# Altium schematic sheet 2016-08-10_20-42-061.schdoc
size 331 x 134 mm; SheetNumber: 1; SheetTotal: 1
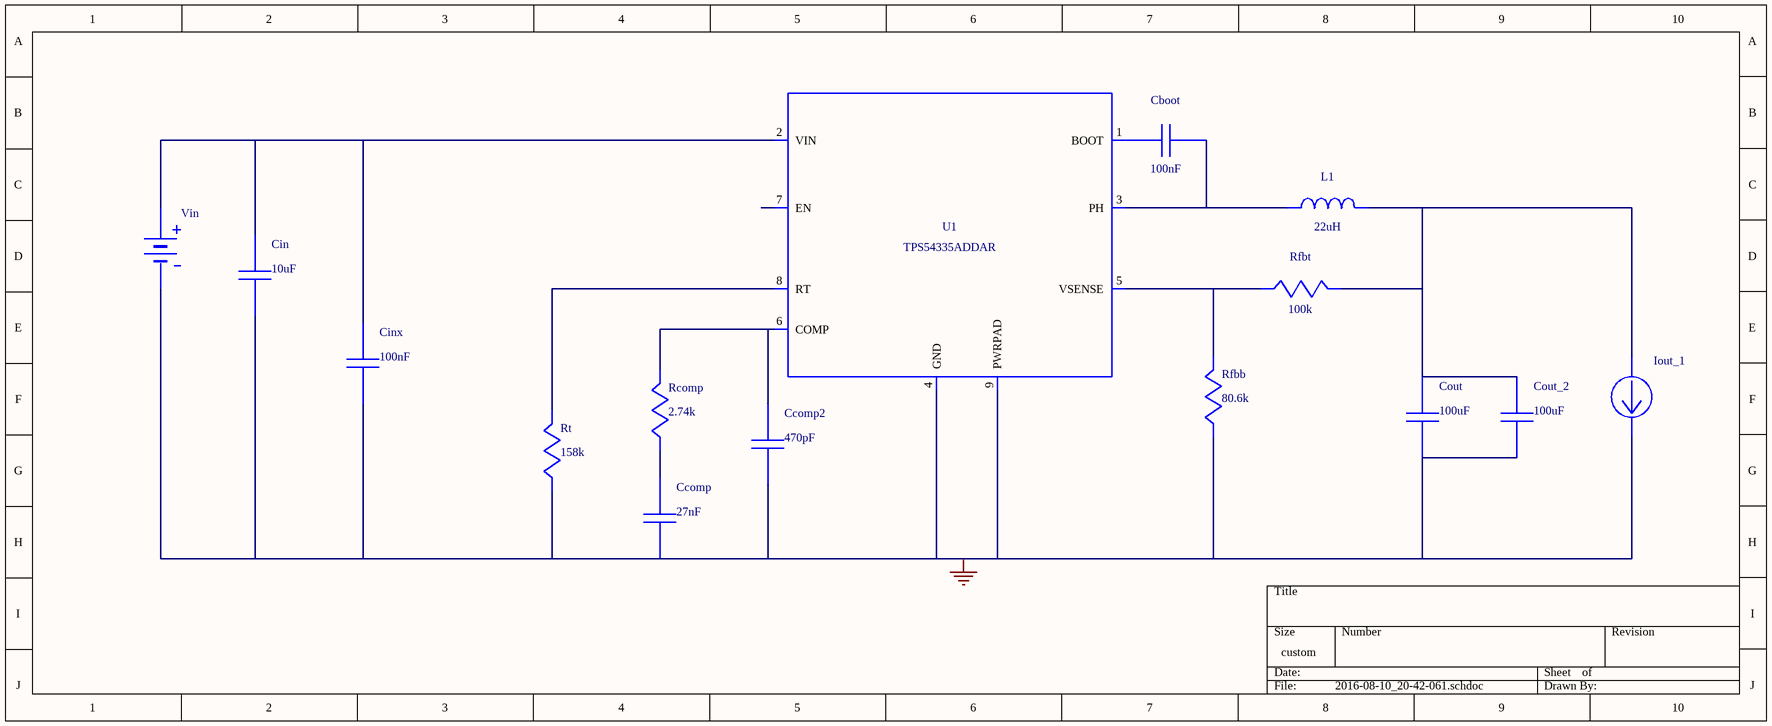
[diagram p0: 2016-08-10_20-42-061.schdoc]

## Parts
Cboot  value 100nF  (hidden comment: C0805C104K5RACTU)
Ccomp  value 27nF  (hidden comment: GRM155R61A273KA01D)
Ccomp2  value 470pF  (hidden comment: CC0805KRX7R9BB471)
Cin  value 10uF  (hidden comment: GRM31CR61E106KA12L)
Cinx  value 100nF  (hidden comment: C0805C104K5RACTU)
Cout  value 100uF  (hidden comment: GRM31CD80G107ME39L)
Cout_2  value 100uF  (hidden comment: GRM31CD80G107ME39L)
Iout_1  WB_CURRENT_LOAD  (value not drawn)
L1  value 22uH  (hidden comment: VLP8040T-220M)
Rcomp  value 2.74k  (hidden comment: CRCW04022K74FKED)
Rfbb  value 80.6k  (hidden comment: CRCW040280K6FKED)
Rfbt  value 100k  (hidden comment: CRCW0402100KFKED)
Rt  value 158k  (hidden comment: CRCW0402158KFKED)
U1  TPS54335ADDAR
Vin  WB_BATTERY  (value not drawn)

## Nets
0: Ccomp.2 Ccomp2.2 Cin.2 Cinx.2 Cout.2 Cout_2.2 Iout_1.2(-) Rfbb.2 Rt.2 U1.4(GND) U1.9(PWRPAD) Vin.2(-)
NetCboot_1: Cboot.1 U1.1(BOOT)
NetCboot_2: Cboot.2 L1.1 U1.3(PH)
NetCcomp2_1: Ccomp2.1 Rcomp.1 U1.6(COMP)
NetCcomp_1: Ccomp.1 Rcomp.2
NetCin_1: Cin.1 Cinx.1 U1.2(VIN) Vin.1(+)
NetCout_1: Cout.1 Cout_2.1 Iout_1.1(+) L1.2 Rfbt.1
NetRfbb_1: Rfbb.1 Rfbt.2 U1.5(VSENSE)
NetRt_1: Rt.1 U1.8(RT)

Not connected (* = marked no-connect by the designer): U1 7(EN)

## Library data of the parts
Cboot Cinx = C0805C104K5RACTU: Manufacturer Name: Kemet
Ccomp = GRM155R61A273KA01D: GRM155R61A273KA0; Manufacturer Name: MuRata
Ccomp2 = CC0805KRX7R9BB471: CC0805KRX7R9BB47; Manufacturer Name: Yageo America
Cin = GRM31CR61E106KA12L: GRM31CR61E106KA1; Manufacturer Name: MuRata
Cout Cout_2 = GRM31CD80G107ME39L: GRM31CD80G107ME3; Manufacturer Name: MuRata
L1 = VLP8040T-220M: Unknown; Manufacturer Name: TDK
Rcomp = CRCW04022K74FKED: Manufacturer Name: Vishay-Dale
Rfbb = CRCW040280K6FKED: Manufacturer Name: Vishay-Dale
Rfbt = CRCW0402100KFKED: Manufacturer Name: Vishay-Dale
Rt = CRCW0402158KFKED: Manufacturer Name: Vishay-Dale
U1 = TPS54335ADDAR: Manufacturer Name: Texas Instruments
